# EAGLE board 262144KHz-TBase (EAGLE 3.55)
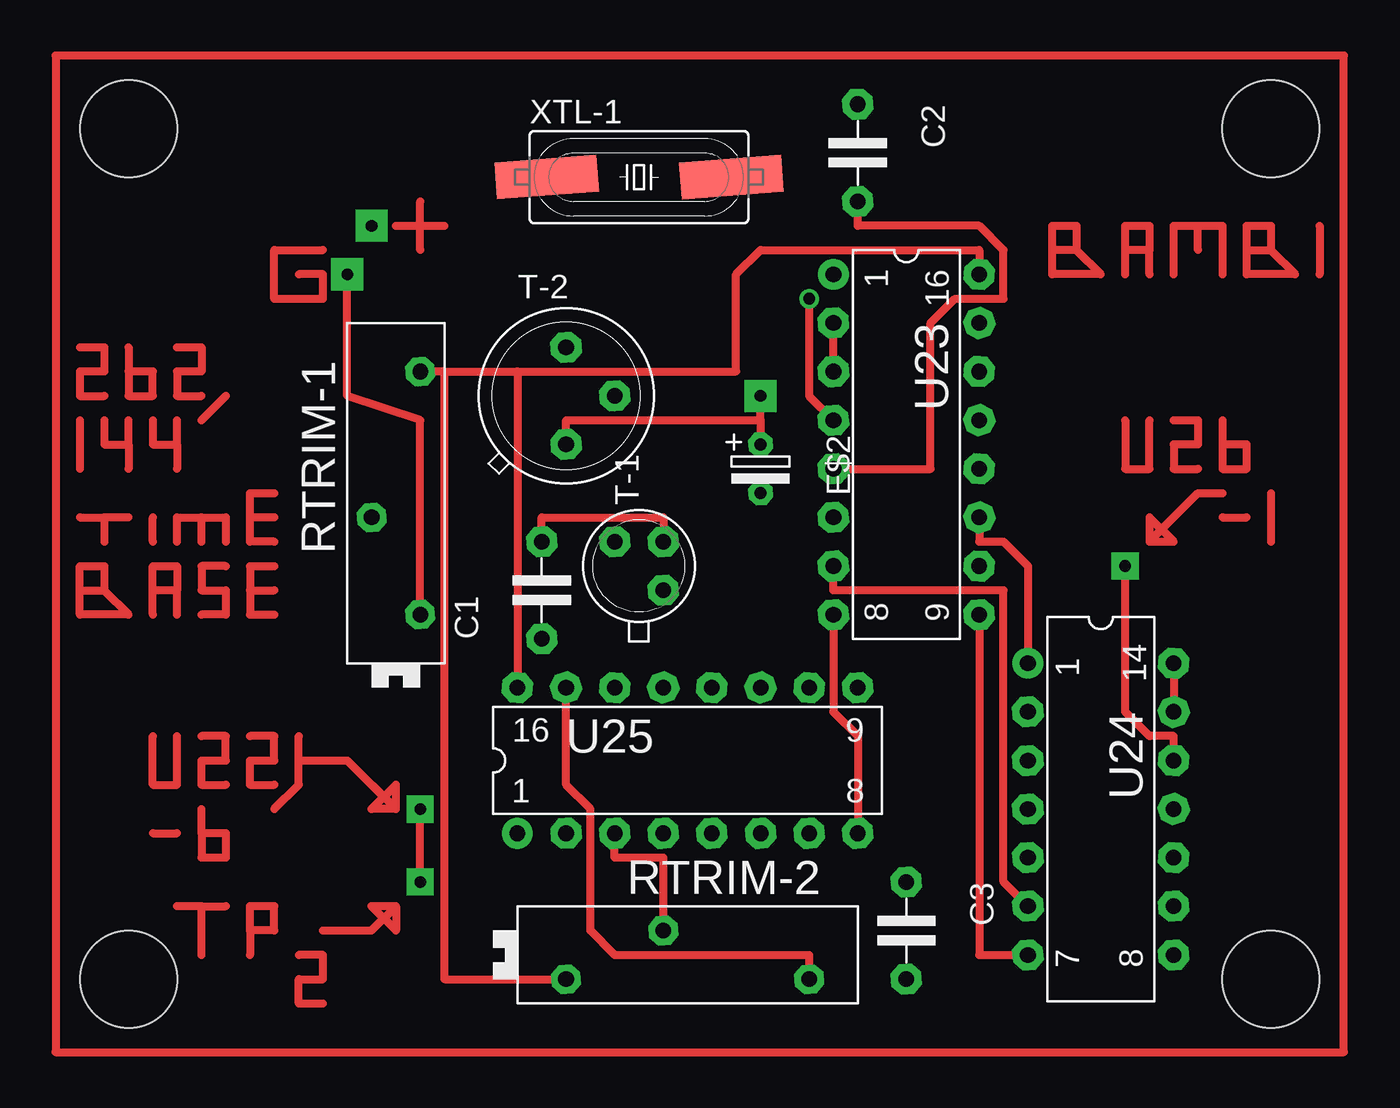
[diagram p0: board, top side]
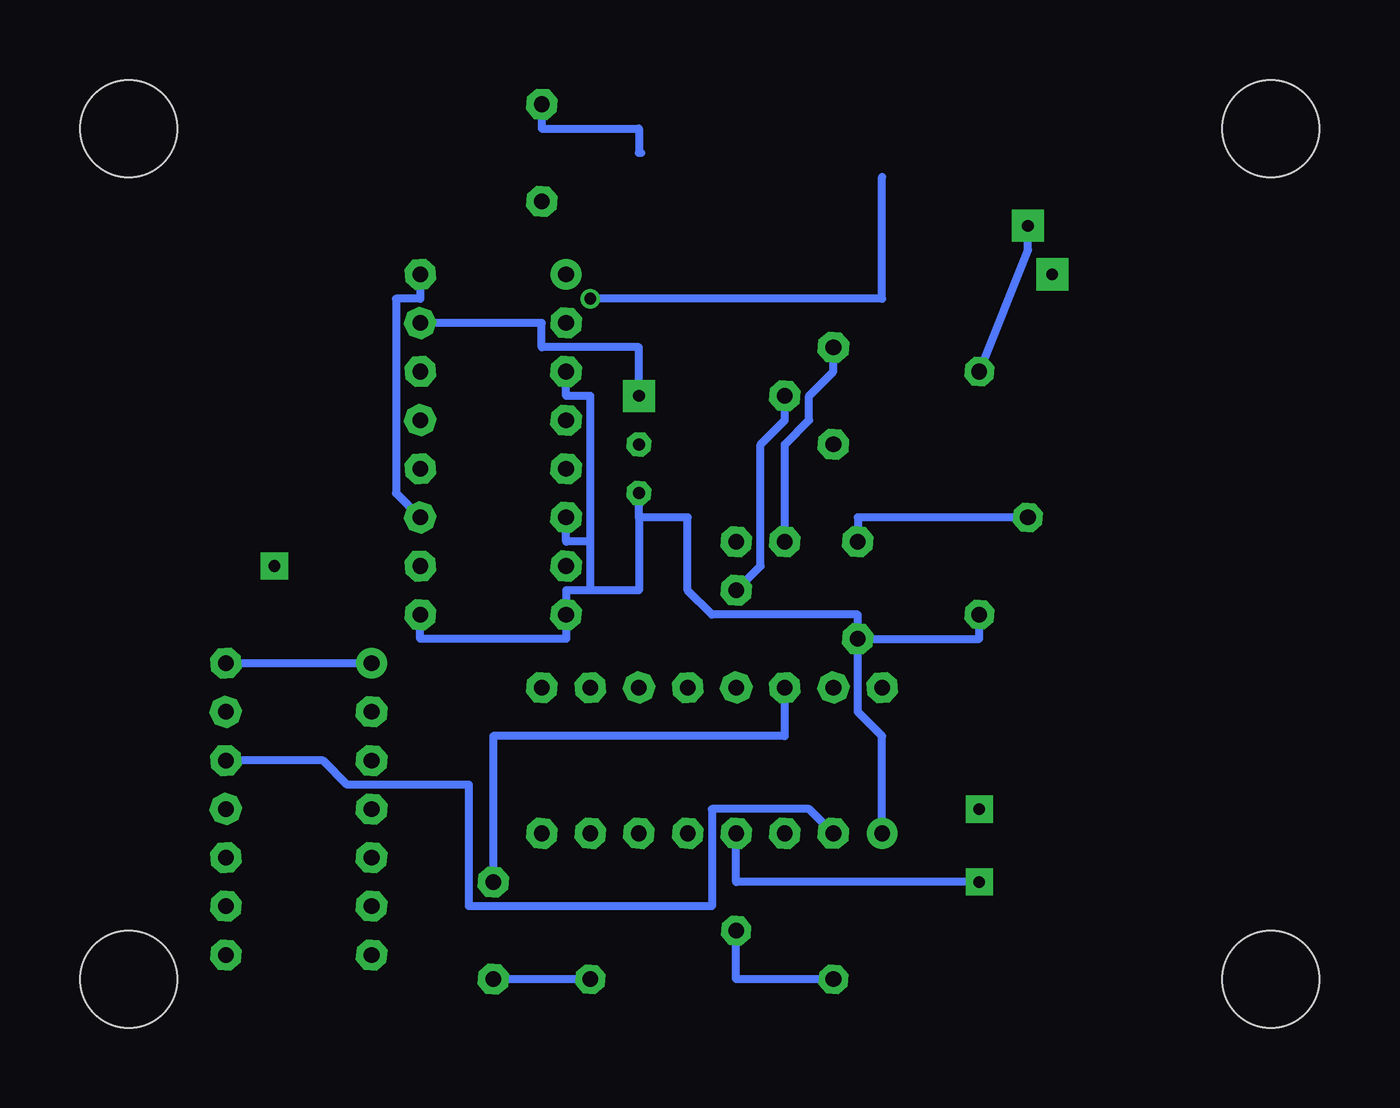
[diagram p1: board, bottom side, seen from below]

No outline drawn. Coordinates in mm, seen from the top.
Copper layers used: Top, Bottom
Holes 5.08 mm at -3.81,88.9 55.88,88.9 55.88,44.45 -3.81,44.45

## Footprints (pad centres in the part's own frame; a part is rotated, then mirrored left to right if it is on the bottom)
5 = drill 0.813 pad 1.6 octagon:  -2.54,0;  2.54,0
-2,5 = drill 0.61 pad 1.27 octagon:  -1.27,0;  1.27,0
-SPIN = drill 0.813 pad 1.524 octagon:  -1.27,1.27;  6.35,-1.27;  -6.35,-1.27
18 = drill 0.813 pad 1.6 octagon:  -1.27,-1.27;  1.27,-1.27;  1.27,1.27
5' = drill 0.813 pad 1.6 octagon:  0,-2.54;  2.54,0;  0,2.54
L16 = drill 0.813 pad 1.6 round:  -8.89,-3.81 | drill 0.813 pad 1.6 octagon:  -6.35,-3.81;  -3.81,-3.81;  -1.27,-3.81;  1.27,-3.81;  3.81,-3.81;  6.35,-3.81;  8.89,-3.81;  8.89,3.81;  6.35,3.81;  3.81,3.81;  1.27,3.81;  -1.27,3.81;  -3.81,3.81;  -6.35,3.81;  -8.89,3.81
L14 = drill 0.813 pad 1.6 round:  -7.62,-3.81 | drill 0.813 pad 1.6 octagon:  -5.08,-3.81;  -2.54,-3.81;  0,-3.81;  2.54,-3.81;  5.08,-3.81;  7.62,-3.81;  7.62,3.81;  5.08,3.81;  2.54,3.81;  0,3.81;  -2.54,3.81;  -5.08,3.81;  -7.62,3.81
49UP = smd 5.334 x 1.93 rotated 4.3:  -4.826,0 | smd 5.334 x 1.93 rotated 4.4:  4.826,0

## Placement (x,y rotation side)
C1  .1uF  [5]  17.78,64.77 90 top
C2  4pF  [5]  34.29,87.63 270 top
C3  [5]  36.83,46.99 270 top
E$2  [-2,5]  29.21,71.12 270 top
RTRIM-1  10K  [-SPIN]  10.16,69.85 90 top
RTRIM-2  100K  [-SPIN]  25.4,45.72 0 top
T-1  2N2222  [18]  22.86,66.04 90 top
T-2  2N3053  [5']  19.05,74.93 0 top
U23  74LS124  [L16]  36.83,72.39 270 top
U24  74177  [L14]  46.99,53.34 270 top
U25  74LS123  [L16]  25.4,55.88 0 top
XTL-1  2.097152MHz  [49UP]  22.86,86.36 0 top

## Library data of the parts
C1-C3 E$2 RTRIM-1 RTRIM-2 = discrete
T-1 T-2 = pnp
U23-U25 = 74xx
XTL-1 = quartz

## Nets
S$1: T-1. T-2.
S$2: C1. RTRIM-1. T-1.
S$3: U23.
S$4: C3. RTRIM-2. U25.
S$8: T-1. T-2.
S$10: E$2. T-2. U23.
S$11: C1. E$2. RTRIM-1. U23. U24. U25.
S$12: C2. U23.
S$13: RTRIM-1. RTRIM-2. U23. U24. U25.
S$14: C3. U25.
S$15: U25.
S$27: U24. U25.
S$28: U23. U24.
S$55: C2.

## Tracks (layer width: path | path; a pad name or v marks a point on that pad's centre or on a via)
S$1
  Bottom 0.406: T-1. 21.59,72.39 20.32,73.66 20.32,74.93 19.05,76.2 T-2.
S$2
  Top 0.406: 24.13,67.31 24.13,68.58 17.78,68.58 C1.
  Bottom 0.406: 8.89,68.58 17.78,68.58 C1.
S$3  (via drill 0.61 pad 1.02)
  Top 0.406: 33.02,73.66 31.75,74.93 v31.75,80.01
  Bottom 0.406: v31.75,80.01 16.51,80.01 16.51,86.36
S$4
  Top 0.406: 19.05,59.69 19.05,54.61 20.32,53.34 20.32,46.99 21.59,45.72 31.75,45.72 31.75,44.45
  Bottom 0.406: 31.75,44.45 C3.
S$5
  Top 0.406: 11.43,82.55 11.43,85.09
S$6
  Top 0.406: 10.16,83.82 12.7,83.82
S$7
  Top 0.406: 6.35,82.55 3.81,82.55 3.81,80.01 6.35,80.01 6.35,81.28 5.08,81.28
S$8
  Bottom 0.406: 24.13,64.77 22.86,66.04 22.86,72.39 21.59,73.66 21.59,74.93
S$10  (via drill 0.61 pad 1.68)
  Top 0.406: 29.21,73.66 29.21,72.39 | 29.21,73.66 v29.21,74.93 | 29.21,73.66 19.05,73.66 19.05,72.39
  Bottom 0.406: 40.64,78.74 34.29,78.74 34.29,77.47 29.21,77.47 v29.21,74.93
S$11  (via drill 0.61 pad 1.68)
  Top 0.406: RTRIM-1. 11.43,73.66 7.62,74.93 v7.62,81.28 | 33.02,76.2 33.02,78.74 | 34.29,52.07 34.29,57.15 33.02,58.42 33.02,63.5 | 43.18,45.72 40.64,45.72 40.64,63.5
  Bottom 0.406: 17.78,62.23 11.43,62.23 RTRIM-1. | 29.21,68.58 E$2. | 29.21,68.58 26.67,68.58 26.67,64.77 25.4,63.5 17.78,63.5 17.78,62.23 | 31.75,64.77 29.21,64.77 29.21,68.58 | 31.75,64.77 33.02,64.77 33.02,63.5 33.02,62.23 40.64,62.23 40.64,63.5 | 33.02,68.58 33.02,67.31 31.75,67.31 | 31.75,64.77 31.75,67.31 | 33.02,76.2 33.02,74.93 31.75,74.93 31.75,67.31 | 16.51,52.07 16.51,57.15 17.78,58.42 17.78,62.23
S$12
  Top 0.406: 33.02,71.12 38.1,71.12 38.1,78.74 39.37,80.01 41.91,80.01 41.91,82.55 40.64,83.82 34.29,83.82 C2.
S$13  (via drill 0.61 pad 1.68)
  Top 0.406: 12.7,76.2 11.43,76.2 | 12.7,76.2 16.51,76.2 | 16.51,76.2 27.94,76.2 27.94,81.28 29.21,82.55 40.64,82.55 U23. | RTRIM-2. 12.7,44.45 12.7,76.2 | 16.51,76.2 U25. | 21.59,52.07 21.59,50.8 24.13,50.8 24.13,46.99 | U24. 50.8,58.42 | 43.18,60.96 43.18,66.04 41.91,67.31 40.64,67.31 40.64,68.58
  Bottom 0.406: 11.43,76.2 8.89,82.55 v8.89,83.82 | 40.64,68.58 41.91,69.85 41.91,80.01 40.64,80.01 U23. | RTRIM-2. 24.13,44.45 24.13,46.99 | 43.18,60.96 U24.
S$14
  Bottom 0.406: 21.59,59.69 21.59,57.15 36.83,57.15 36.83,49.53
S$15  (via drill 0.61 pad 1.42)
  Top 0.406: v11.43,49.53 v11.43,53.34
  Bottom 0.406: 24.13,52.07 24.13,49.53 v11.43,49.53
S$16
  Top 0.406: 10.16,48.26 8.89,48.26 10.16,46.99 10.16,48.26 | 10.16,48.26 8.89,46.99 6.35,46.99
S$17
  Top 0.406: 10.16,53.34 8.89,54.61 | 10.16,53.34 10.16,54.61 8.89,53.34 10.16,53.34 | 10.16,53.34 7.62,55.88 5.08,55.88 | 5.08,55.88 5.08,57.15 | 5.08,55.88 5.08,54.61 3.81,53.34
S$18
  Top 0.406: -2.54,57.15 -2.54,54.61 -1.27,54.61 -1.27,57.15
S$19
  Top 0.406: 0,57.15 1.27,57.15 1.27,55.88 0,55.88 0,54.61 1.27,54.61
S$20
  Top 0.406: 2.54,57.15 3.81,57.15 3.81,55.88 2.54,55.88 2.54,54.61 3.81,54.61
S$21
  Top 0.406: -2.54,52.07 -1.27,52.07
S$22
  Top 0.406: 0,52.07 0,53.34 | 0,52.07 0,50.8 1.27,50.8 1.27,52.07 0,52.07
S$23
  Top 0.406: 0,48.26 -1.27,48.26 | 0,48.26 1.27,48.26 | 0,45.72 0,48.26
S$24
  Top 0.406: 2.54,46.99 2.54,45.72 | 2.54,46.99 2.54,48.26 3.81,48.26 3.81,46.99 2.54,46.99
S$25
  Top 0.406: 5.08,45.72 6.35,45.72 6.35,44.45 5.08,44.45 5.08,43.18 6.35,43.18
S$26
  Top 0.406: 49.53,67.31 49.53,68.58 50.8,67.31 49.53,67.31 | 49.53,67.31 52.07,69.85 53.34,69.85
S$27  (via drill 0.61 pad 1.42)
  Top 0.406: v48.26,66.04 48.26,58.42 49.53,57.15 50.8,57.15 50.8,55.88
  Bottom 0.406: 19.05,52.07 20.32,53.34 25.4,53.34 25.4,48.26 38.1,48.26 38.1,54.61 44.45,54.61 45.72,55.88 50.8,55.88
S$28
  Top 0.406: 43.18,48.26 41.91,49.53 41.91,64.77 33.02,64.77 33.02,66.04
S$29
  Top 0.406: 48.26,73.66 48.26,71.12 49.53,71.12 49.53,73.66
S$30
  Top 0.406: 50.8,73.66 52.07,73.66 52.07,72.39 50.8,72.39 50.8,71.12 52.07,71.12
S$31
  Top 0.406: 53.34,73.66 53.34,72.39 | 53.34,72.39 53.34,71.12 54.61,71.12 54.61,72.39 53.34,72.39
S$32
  Top 0.406: 53.34,68.58 54.61,68.58
S$33
  Top 0.406: 55.88,69.85 55.88,67.31
S$34
  Top 0.406: -7.62,92.71 -7.62,40.64 59.69,40.64 59.69,92.71 -7.62,92.71
S$35
  Top 0.406: 44.45,82.55 44.45,81.28 46.99,81.28 45.72,82.55 | 44.45,82.55 44.45,83.82 45.72,83.82 45.72,82.55 | 45.72,82.55 44.45,82.55
S$36
  Top 0.406: 48.26,81.28 48.26,82.55 | 48.26,82.55 48.26,83.82 49.53,83.82 49.53,82.55 | 49.53,81.28 49.53,82.55 | 49.53,82.55 48.26,82.55
S$37
  Top 0.406: 50.8,81.28 50.8,83.82 52.07,83.82 | 52.07,82.55 52.07,83.82 | 52.07,83.82 53.34,83.82 53.34,81.28
S$38
  Top 0.406: 54.61,82.55 54.61,81.28 57.15,81.28 55.88,82.55 | 54.61,82.55 54.61,83.82 55.88,83.82 55.88,82.55 | 54.61,82.55 55.88,82.55
S$39
  Top 0.406: 58.42,83.82 58.42,81.28
S$40
  Top 0.406: -6.35,77.47 -5.08,77.47 -5.08,76.2 -6.35,76.2 -6.35,74.93 -5.08,74.93
S$41
  Top 0.406: -3.81,77.47 -3.81,76.2 | -3.81,76.2 -3.81,74.93 -2.54,74.93 -2.54,76.2 -3.81,76.2
S$42
  Top 0.406: -1.27,77.47 0,77.47 0,76.2 -1.27,76.2 -1.27,74.93 0,74.93
S$43
  Top 0.406: 1.27,74.93 0,73.66
S$44
  Top 0.406: -6.35,73.66 -6.35,71.12
S$45
  Top 0.406: -5.08,73.66 -5.08,72.39 -3.81,72.39 | -3.81,72.39 -3.81,73.66 | -3.81,72.39 -3.81,71.12
S$46
  Top 0.406: -2.54,73.66 -2.54,72.39 -1.27,72.39 | -1.27,72.39 -1.27,73.66 | -1.27,72.39 -1.27,71.12
S$47
  Top 0.406: -6.35,68.58 -5.08,68.58 | -3.81,68.58 -5.08,68.58 | -5.08,68.58 -5.08,67.31
S$48
  Top 0.406: -2.54,67.31 -2.54,68.58
S$49
  Top 0.406: -1.27,67.31 -1.27,68.58 0,68.58 | 0,67.31 0,68.58 | 0,68.58 1.27,68.58 1.27,67.31
S$50
  Top 0.406: 3.81,67.31 2.54,67.31 2.54,68.58 | 3.81,68.58 2.54,68.58 | 2.54,68.58 2.54,69.85 3.81,69.85
S$51
  Top 0.406: -6.35,64.77 -6.35,63.5 -3.81,63.5 -5.08,64.77 | -6.35,64.77 -6.35,66.04 -5.08,66.04 -5.08,64.77 | -6.35,64.77 -5.08,64.77
S$52
  Top 0.406: -2.54,63.5 -2.54,64.77 | -2.54,64.77 -2.54,66.04 -1.27,66.04 -1.27,64.77 | -1.27,63.5 -1.27,64.77 | -1.27,64.77 -2.54,64.77
S$53
  Top 0.406: 1.27,66.04 0,66.04 0,64.77 1.27,64.77 1.27,63.5 0,63.5
S$54
  Top 0.406: 2.54,64.77 2.54,66.04 3.81,66.04 | 2.54,64.77 2.54,63.5 3.81,63.5 | 2.54,64.77 3.81,64.77
S$55
  Bottom 0.406: 29.08,87.63 29.21,87.63 29.21,88.9 34.29,88.9 34.29,90.17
